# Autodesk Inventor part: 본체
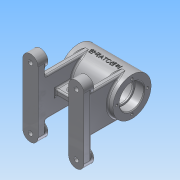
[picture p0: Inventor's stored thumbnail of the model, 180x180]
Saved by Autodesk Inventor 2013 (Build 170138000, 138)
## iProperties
Created: 2015-11
Part Number: 본체
Material: 알루미늄 6061
Document SubType Name: Modeling
Designer: Administrator
Density: 2.71 g/cm^3
Mass: 373.368 g
Surface Area: 453.781 cm^2
Volume: 137.774 cm^3
Author: Administrator
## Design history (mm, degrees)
sketch "스케치1"
  geometry: L1 (35, 0)-(-35, 0); L2 (-35, 25)-(35, 25); L3 (35, 25)-(35, 16); L4 (35, 16)-(23, 16); L5 (23, 16)-(23, 14); L6 (23, 14)-(21, 14); L7 (21, 14)-(21, 21); L8 (21, 21)-(-21, 21); L9 (-21, 21)-(-21, 14); L10 (-21, 14)-(-23, 14); L11 (-23, 14)-(-23, 16); L12 (-23, 16)-(-35, 16); L13 (-35, 16)-(-35, 25); 2 further points
  constraints: 26 end point, 10 parallel, 2 perpendicular, 1 coincident, 1 horizontal, 1 midpoint, 1 vertical alignment
  dimensions: "d1" = 70 distance of L1.start L1.end; "d3" = 70 distance of L2.start L2.end; "d5" = 32 diameter of L12 L1; "d6" = 50 diameter of L2 L1; "d7" = 28 diameter of L10 L1; "d8" = 32 diameter of L4 L1; "d9" = 28 diameter of L6 L1; "d10" = 42 diameter of L8 L1; "d11" = 2 distance between parallel lines of L9 L11; "d12" = 2 distance between parallel lines of L7 L5; "d13" = 12 distance between parallel lines of L13 L11; "d14" = 12 distance between parallel lines of L3 L5
revolve "회전1" sketch "스케치1" stored, may be unused: angle "d15" = 90 deg
chamfer "모따기1" distance "d16" = 1; stored, may be unused: second distance "d17" = 2, angle "d18" = 45 deg
fillet "모깎기1" dims "d19" = 0.3
node "작업 평면1"
sketch "스케치3"
  geometry: L1 (40, -40)-(40, 40); L2 (-20, 40)-(-20, -40); L3 (20, 40)-(20, -40); L4 (-40, -40)-(-40, 40); A1 r 10 centre (30, 40) between (40, 40) and (20, 40); A2 r 10 centre (-30, 40) between (-20, 40) and (-40, 40); A3 r 10 centre (-30, -40) between (-20, -40) and (-40, -40); A4 r 10 centre (30, -40) between (40, -40) and (20, -40); 2 further points
  constraints: 8 end point, 8 point on circle, 7 tangent, 4 centre point, 3 equal radius, 3 horizontal alignment, 2 vertical alignment, 1 midpoint, 1 vertical
  dimensions: "d33" = 20 diameter of A4; "d36" = 40 distance from line of L1 point (0, 0); "d37" = 40 distance from line of L4 point (0, 0); "d38" = 80 distance of A3.centre A2.centre
extrude "돌출3" join sketch "스케치3" distance "d39" = 10; taper "d40" = 0 deg
extrude "돌출4" join sketch "스케치3" distance "d41" = 13; taper "d42" = 0 deg
sketch "스케치4"
  geometry: L1 (40, -40)-(40, 40) reference; L2 (20, -25)-(20, 25); L3 (20, 25)-(28, 25); L4 (28, 25)-(28, -25); L5 (28, -25)-(20, -25); 2 further points
  constraints: 8 end point, 2 parallel, 1 horizontal alignment, 1 midpoint, 1 perpendicular
  dimensions: "d44" = 50 distance of L2.start L2.end; "d46" = 20 distance from line of L2 point (0, 0); "d47" = 8 distance of L2.end L3.end; "d48" = 50 distance of L3.end L4.end
extrude "돌출5" join sketch "스케치4" stored distance "d49" = 13; taper "d50" = 0 deg
node "작업 평면2"
sketch "스케치6"
  geometry: L1 (20, -4)-(-20, -4); L2 (-20, -4)-(-20, 4); L3 (-20, 4)-(20, 4); L4 (20, 4)-(20, -4); L5 (20, -4)-(-20, 4); L6 (-20, -4)-(20, 4); 1 further point
  constraints: 12 end point, 2 midpoint, 2 parallel, 1 horizontal, 1 perpendicular
  dimensions: "d54" = 8 distance between parallel lines of L1 L3; "d56" = 40 distance between parallel lines of L2 L4
extrude "돌출6" join sketch "스케치6" stored distance "d57" = 13; taper "d58" = 0 deg
sketch "스케치7"
  geometry: L1 (0, 20.322)-(40, 20.322) reference; L2 (12, 13.5)-(28, 13.5); L3 (28, 6.5)-(12, 6.5); L4 (60, -23)-(40, -23) reference; A1 r 3.5 centre (12, 10) between (12, 13.5) and (12, 6.5); A2 r 3.5 centre (28, 10) between (28, 6.5) and (28, 13.5); 2 further points
  constraints: 4 end point, 4 point on circle, 3 tangent, 2 centre point, 1 horizontal alignment, 1 midpoint, 1 parallel, 1 vertical alignment
  dimensions: "d59" = 7 diameter of A1; "d60" = 7 diameter of A2; "d61" = 33 distance from line of A2.centre L4; "d62" = 23 dimension on A1 A2
extrude "돌출7" cut sketch "스케치7" stored distance "d63" = 13; taper "d64" = 0 deg
node "작업 평면3"
sketch "스케치8"
  geometry: C1 r 5 at (0, 0); 1 further point
  constraints: 1 centre point, 1 coincident
  dimensions: "d66" = 10 diameter of C1
extrude "돌출8" join sketch "스케치8" stored distance "d67" = 13; taper "d68" = 0 deg
sketch "스케치9"
  geometry: L1 (-45, 4)-(-38.5, 4) reference; L2 (-38.5, 4)-(-38.5, -4) reference; L3 (-38.5, -4)-(-45, -4) reference; L4 (-45, -4)-(-45, 4) reference; L5 (-31.5, 4)-(-24.678, 4) reference; L6 (24.495, 5)-(28, 5) reference; L7 (28, 5)-(28, -5) reference; L8 (28, -5)-(24.495, -5) reference; L9 (-24.678, -4)-(-31.5, -4) reference; L10 (-31.5, -4)-(-31.5, 4) reference; L11 (0, 0)-(-24.249, -14); L12 (0, 0)-(-7.726, 0); C1 r 21 at (0, 0) reference; A1 r 25 centre (0, 0) between (24.495, 5) and (-24.678, 4) reference; A2 r 25 centre (0, 0) between (-24.678, -4) and (24.495, -5) reference; 1 further point
  constraints: 4 end point, 1 perpendicular
  dimensions: "d70" = 28 distance of L11.start L11.end; "d71" = 30 deg angle of L12 L11
  node "절단 모서리 투영1"
node "작업 평면4"
sketch "스케치10"
  geometry: C1 r 6 at (0, 0); 1 further point
  constraints: 1 centre point, 1 coincident
  dimensions: "d72" = 12 diameter of C1
extrude "돌출9" join sketch "스케치10" stored distance "d73" = 13; taper "d74" = 0 deg
hole "구멍1" diameter "d77" = 6; stored, may be unused: countersink angle "d81" = 90 deg, drill point angle "d83" = 118 deg; dims "d75" = 10, "d76" = 10, "d78" = 6, "d79" = 12, "d80" = 4, "d82" = 8
fillet "모깎기2" dims "d84" = 0.3
chamfer "모따기2" distance "d85" = 1; stored, may be unused: second distance "d86" = 2, angle "d87" = 45 deg
hole "구멍2" diameter "d90" = 5.188; stored, may be unused: countersink angle "d94" = 90 deg, drill point angle "d96" = 118 deg; dims "d88" = 10, "d89" = 10, "d91" = 6, "d92" = 1, "d93" = 4, "d95" = 8
hole "구멍3" diameter "d99" = 5.188; stored, may be unused: countersink angle "d103" = 90 deg, drill point angle "d105" = 118 deg; dims "d97" = 10, "d98" = 10, "d100" = 6, "d101" = 1, "d102" = 4, "d104" = 8
sketch "스케치11"
  geometry: C1 r 25 at (0, 0) reference; 1 further point
  constraints: 1 vertical alignment
  dimensions: "d106" = 20 distance of point (0, 20) C1.centre
hole "구멍4" sketch "스케치11" at (0, 20) diameter "d107" = 3.242; stored, may be unused: countersink angle "d111" = 90 deg, drill point angle "d113" = 118 deg; dims "d108" = 8, "d109" = 1, "d110" = 4, "d112" = 10
fillet "모깎기3" dims "d117" = 2
fillet "모깎기4" dims "d118" = 3
node "작업 평면5"
sketch "스케치12"
  geometry: L1 (-35, -25)-(-35, 25) reference; L2 (-35, 25)-(35, 25) reference; 2 further points
  constraints: 1 other
  dimensions: "d119" = 35 distance from line of point (0, 0) L1; "d120" = 25 distance from line of point (0, 0) L2
feature "엠보싱1" sketch "스케치12" dims "d1" = 70, "d121" = 0.5, "d122" = 0
node "솔리드1"
mirror "대칭1"
mirror "대칭2"
mirror "대칭3"
pattern_circular "원형 패턴1" dims angle "d115" = 360 deg
mirror "대칭4"
other parameters: "d20" = -68, "d53" = -45, "d65" = 28
